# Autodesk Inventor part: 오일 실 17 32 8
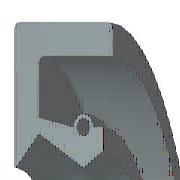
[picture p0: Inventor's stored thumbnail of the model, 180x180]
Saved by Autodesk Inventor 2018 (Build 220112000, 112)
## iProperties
IsCustomPart: 0
Created: 2018-09
Part Number: 오일 실 17 32 8
Material: 고무
Description: 오일-실
Document SubType Name: Modeling
Standard: KS B 2804
Standards Organization: KS
Language: ko-KR
Size Designation: D - 17 32 8
Categories: <MemberInstance><Categories><Category DisplayName="샤프트 부품" InternalName="7f7aeb1f-a693-4053-b835-cee3144e0d98" Mnemonic="SHFT"><Category DisplayName="실링" Intern
Density: 0.93 g/cm^3
Mass: 2.28027 g
Surface Area: 32.1224 cm^2
Volume: 2.45191 cm^3
Appearance: 고무 - 검은색 - 버전 1.1
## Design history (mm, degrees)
revolve "본체" stored, may be unused: angle "d17" = 90 deg
revolve "스프링1" stored, may be unused: angle "d18" = 90 deg
body "Solid1"
sketch "스케치1"
  geometry: L1 (0, 16)-(8, 16); L2 (8, 14.25)-(1.75, 14.25); L3 (1.75, 10.25)-(4.9, 8.5); L4 (4.9, 8.5)-(0, 8.5); L5 (0, 0)-(9.586, 0) reference; L6 (4.9, 8.5)-(6.3, 9.375); L7 (0, 18)-(0, -3) reference; L8 (-1.941, 0)-(11.507, 0) reference; L9 (4.2, 10.6)-(1.75, 11.21); L10 (1.75, 11.21)-(1.75, 14.25); L11 (0, 16)-(0, 8.588); L12 (4.9, 8.5)-(0, 8.5); L13 (1.75, 10.25)-(0.152, 8.528); L14 (8, 16)-(8, 14.25); L15 (5.6, 10.6)-(6.3, 10.6); L16 (6.3, 10.6)-(6.3, 9.375); C1 r 0.455 at (4.9, 10.6); A1 r 0.7 centre (4.9, 10.6) between (5.6, 10.6) and (4.2, 10.6); A2 r 0.088 centre (0.088, 8.588) between (0, 8.588) and (0.152, 8.528); 1 further point
  constraints: 28 end point, 5 horizontal alignment, 5 point on line, 4 point on circle, 4 vertical alignment, 3 centre point, 3 tangent, 2 collinear, 2 horizontal, 2 perpendicular, 1 coincident, 1 parallel
  dimensions: "d0" = 32 diameter of L1 L5 (= SD2); "d1" = 1.75 distance of L1.end L2.start (= SD); "d2" = 0.91 diameter of C1 (= SPDI); "d3" = 1.4 diameter of A1 (= SPDA); "d4" = 17 diameter of L3.end L5 (= NND); "d5" = 20.5 diameter of L3.start L5 (= TKDM); "d7" = 22.42 diameter of L9.end L5 (= TKDM + 0.24 x SWDT); "d8" = 1.75 distance between parallel lines of L11 L10 (= SD); "d9" = 4.9 distance from line of L11 C1.centre (= SPDST); "d10" = 21.2 diameter of C1.centre L5 (= HLDM); "d11" = 0.0875 radius of A2 (= 0.25 x LAB); "d12" = 6.3 distance between parallel lines of L11 L16 (= SDI); "d13" = 18.75 diameter of L6.end L5 (= ABDM); "d14" = 8 distance from line of L11 L1.end (= SWDT)
fillet "모깎기1" dims "d6" = 0.3 (= RR)
other parameters: "SD2" = 32 [user parameter; used in 1 equation term], "SWDT" = 8 [user parameter; used in 2 equation terms], "RR" = 0.3 [user parameter; used in 1 equation term], "SD" = 1.75 [user parameter; used in 2 equation terms], "NND" = 17 [user parameter; used in 1 equation term], "SPDA" = 1.4 [user parameter; used in 1 equation term], "SPDI" = 0.91 [user parameter; used in 1 equation term], "TKDM" = 20.5 [user parameter; used in 2 equation terms], "HLDM" = 21.2 [user parameter; used in 1 equation term], "ABDM" = 18.75 [user parameter; used in 1 equation term], "SDI" = 6.3 [user parameter; used in 1 equation term], "SPDST" = 4.9 [user parameter; used in 1 equation term], "LAB" = 0.35 [user parameter; used in 1 equation term], "d15" = 0, "d16" = 0, "d19" = 0
